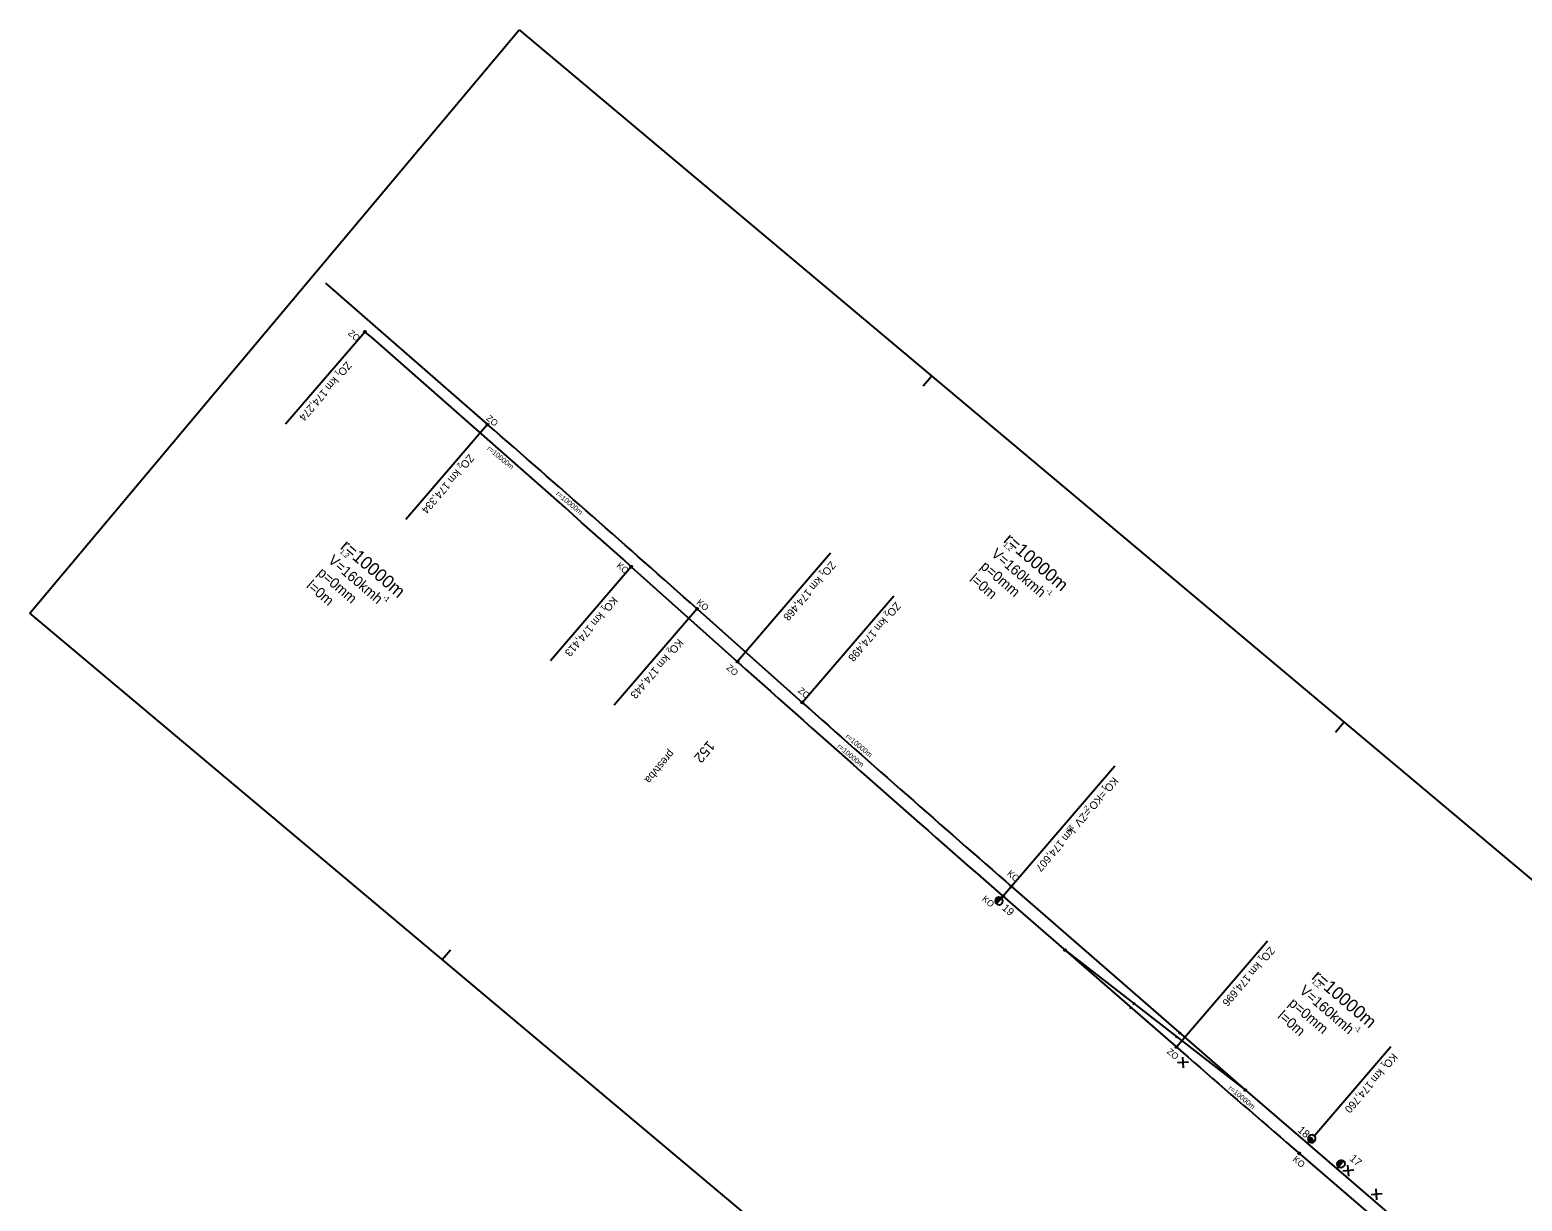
# Model space of a CAD drawing. Extents: x -473608 to -471381, y -1324122 to -1322275.
# Drawn here: x -473608 to -473026, y -1322732 to -1322275 of the extents above; entities that cross this region are included whole.
import ezdxf

# ---------------------------------------------------------------- set-up
doc = ezdxf.new("R2010")
doc.units = 0
for name, color, linetype in [('Level 1', 7, 'Continuous'), ('Level 11', 7, 'Continuous'), ('Level 6', 7, 'Continuous'), ('Level 61', 7, 'Continuous')]:
    doc.layers.add(name, color=color, linetype=linetype)

msp = doc.modelspace()

# ---------------------------------------------------------------- linework, layer by layer
at = {"layer": 'Level 1'}
for p, q in [((-473492.7, -1322373.74), (-473429.48, -1322428.74)), ((-473477.28, -1322392.6), (-473477.28, -1322392.6)), ((-473429.48, -1322428.74), (-473429.48, -1322428.74)), ((-473373.38, -1322484.25), (-473331.98, -1322521.28)), ((-473373.38, -1322484.25), (-473373.38, -1322484.25)), ((-473347.72, -1322500.65), (-473306.68, -1322537.14)), ((-473347.72, -1322500.65), (-473347.72, -1322500.65)), ((-473331.98, -1322521.28), (-473331.98, -1322521.28)), ((-473306.68, -1322537.14), (-473306.68, -1322537.14)), ((-473228.51, -1322612.55), (-473156.12, -1322675.52)), ((-473228.25, -1322612.71), (-473228.25, -1322612.71)), ((-473225, -1322608.92), (-473225, -1322608.92)), ((-473224.87, -1322609.08), (-473133.79, -1322688.32)), ((-473204.14, -1322633.75), (-473204.14, -1322633.75)), ((-473204.14, -1322633.75), (-473133.79, -1322688.32)), ((-473178.81, -1322656.46), (-473178.17, -1322655.69)), ((-473178.49, -1322656.07), (-473178.49, -1322656.07)), ((-473177.58, -1322654.95), (-473176.94, -1322654.18)), ((-473177.26, -1322654.56), (-473177.26, -1322654.56)), ((-473160.95, -1322667.88), (-473160.3, -1322667.11)), ((-473160.62, -1322667.5), (-473160.62, -1322667.5)), ((-473159.73, -1322666.4), (-473159.09, -1322665.63)), ((-473159.41, -1322666.02), (-473159.41, -1322666.02)), ((-473160.67, -1322671.54), (-473160.67, -1322671.54)), ((-473133.79, -1322688.32), (-473109.51, -1322709.21)), ((-473133.79, -1322688.32), (-473133.79, -1322688.32)), ((-473117.89, -1322708.6), (-473035.77, -1322779.3)), ((-473109.51, -1322709.21), (-473066.62, -1322746.14)), ((-473112.8, -1322713.01), (-473112.8, -1322713.01))]:
    msp.add_line(p, q, dxfattribs=at)
for points in [[(-473477.01, -1322392.29), (-473476.88, -1322392.67), (-473477.15, -1322392.97), (-473477.54, -1322392.9), (-473477.67, -1322392.52), (-473477.41, -1322392.22), (-473477.01, -1322392.29)], [(-473429.21, -1322428.44), (-473429.09, -1322428.82), (-473429.35, -1322429.12), (-473429.74, -1322429.04), (-473429.87, -1322428.66), (-473429.61, -1322428.36), (-473429.21, -1322428.44)], [(-473373.64, -1322484.55), (-473373.77, -1322484.17), (-473373.5, -1322483.87), (-473373.11, -1322483.95), (-473372.98, -1322484.33), (-473373.25, -1322484.63), (-473373.64, -1322484.55)], [(-473347.99, -1322500.94), (-473348.11, -1322500.56), (-473347.85, -1322500.27), (-473347.46, -1322500.35), (-473347.33, -1322500.73), (-473347.6, -1322501.03), (-473347.99, -1322500.94)], [(-473331.71, -1322520.98), (-473331.59, -1322521.36), (-473331.85, -1322521.66), (-473332.24, -1322521.58), (-473332.37, -1322521.2), (-473332.1, -1322520.9), (-473331.71, -1322520.98)], [(-473306.41, -1322536.84), (-473306.29, -1322537.22), (-473306.55, -1322537.52), (-473306.94, -1322537.44), (-473307.07, -1322537.06), (-473306.8, -1322536.76), (-473306.41, -1322536.84)], [(-473228.52, -1322613.02), (-473228.65, -1322612.64), (-473228.38, -1322612.34), (-473227.99, -1322612.41), (-473227.86, -1322612.79), (-473228.12, -1322613.09), (-473228.52, -1322613.02)], [(-473225.26, -1322609.23), (-473225.39, -1322608.85), (-473225.13, -1322608.55), (-473224.74, -1322608.62), (-473224.61, -1322609), (-473224.87, -1322609.3), (-473225.26, -1322609.23)], [(-473204.14, -1322634.15), (-473204.48, -1322633.95), (-473204.48, -1322633.55), (-473204.14, -1322633.35), (-473203.79, -1322633.55), (-473203.79, -1322633.95), (-473204.14, -1322634.15)], [(-473160.4, -1322671.24), (-473160.27, -1322671.61), (-473160.54, -1322671.91), (-473160.93, -1322671.84), (-473161.06, -1322671.46), (-473160.8, -1322671.16), (-473160.4, -1322671.24)], [(-473133.79, -1322688.72), (-473134.13, -1322688.52), (-473134.13, -1322688.12), (-473133.79, -1322687.92), (-473133.44, -1322688.12), (-473133.44, -1322688.52), (-473133.79, -1322688.72)], [(-473113.06, -1322713.31), (-473113.2, -1322712.93), (-473112.93, -1322712.63), (-473112.54, -1322712.7), (-473112.41, -1322713.08), (-473112.67, -1322713.38), (-473113.06, -1322713.31)]]:
    msp.add_lwpolyline(points, dxfattribs=at)
for centre, start, end in [((-480040.42, -1329937.47), 48.186756, 48.980589), ((-479992.62, -1329973.62), 48.356833, 48.98065), ((-466665.08, -1315067.93), 228.187894, 228.978408), ((-466661.92, -1315064.04), 228.357864, 228.982058), ((-466593.5, -1315130.19), 228.984525, 229.274253)]:
    msp.add_arc(centre, 10000, start, end, dxfattribs=at)
at = {"layer": 'Level 11'}
for p, q in [((-473477.24, -1322392.63), (-473508.24, -1322428.67)), ((-473429.43, -1322428.76), (-473461.35, -1322465.86)), ((-473373.39, -1322484.31), (-473404.86, -1322520.9)), ((-473295.62, -1322479), (-473331.95, -1322521.24)), ((-473270.96, -1322495.68), (-473306.62, -1322537.15)), ((-473347.8, -1322500.75), (-473380.07, -1322538.26)), ((-473184.68, -1322562.03), (-473228.3, -1322612.74)), ((-473228.3, -1322612.73), (-473230.84, -1322615.76)), ((-473228.3, -1322612.73), (-473228.3, -1322612.73)), ((-473125.19, -1322630.28), (-473160.66, -1322671.53)), ((-473157.92, -1322679.69), (-473158.24, -1322675.43)), ((-473077.05, -1322671.48), (-473106.74, -1322706)), ((-473155.95, -1322677.4), (-473160.22, -1322677.72)), ((-473108.42, -1322705.9), (-473109.02, -1322706.34)), ((-473107.66, -1322705.82), (-473108.42, -1322705.9)), ((-473106.91, -1322706.18), (-473107.66, -1322705.82)), ((-473108.86, -1322708.46), (-473109.51, -1322709.21)), ((-473109.02, -1322706.34), (-473109.37, -1322707.03)), ((-473109.37, -1322707.03), (-473109.33, -1322707.75)), ((-473109.33, -1322707.75), (-473108.86, -1322708.46)), ((-473108.86, -1322708.46), (-473109.33, -1322707.77)), ((-473108.71, -1322706.9), (-473109.15, -1322707.41)), ((-473109.15, -1322707.41), (-473109.06, -1322707.76)), ((-473109.06, -1322707.76), (-473108.37, -1322706.96)), ((-473108.08, -1322707.08), (-473108.89, -1322708.03)), ((-473108.89, -1322708.03), (-473108.86, -1322708.46)), ((-473108.86, -1322708.46), (-473107.83, -1322707.26)), ((-473108.86, -1322708.46), (-473107.83, -1322707.26)), ((-473108.44, -1322708.42), (-473108.86, -1322708.46)), ((-473108.86, -1322708.46), (-473108.11, -1322708.81)), ((-473107.62, -1322707.48), (-473108.44, -1322708.42)), ((-473108.15, -1322708.54), (-473107.46, -1322707.74)), ((-473107.79, -1322708.59), (-473108.15, -1322708.54)), ((-473108.11, -1322708.81), (-473107.4, -1322708.72)), ((-473107.34, -1322708.07), (-473107.79, -1322708.59)), ((-473107.4, -1322708.72), (-473106.75, -1322708.3)), ((-473106.45, -1322706.88), (-473106.91, -1322706.18)), ((-473106.75, -1322708.3), (-473106.44, -1322707.64)), ((-473106.44, -1322707.64), (-473106.45, -1322706.88)), ((-473098.15, -1322719), (-473095.61, -1322715.97)), ((-473093.46, -1322721.85), (-473093.78, -1322717.59)), ((-473098.15, -1322719), (-473098.15, -1322719)), ((-473091.49, -1322719.56), (-473095.75, -1322719.88)), ((-473080.49, -1322728.79), (-473084.76, -1322729.11)), ((-473082.47, -1322731.08), (-473082.79, -1322726.82))]:
    msp.add_line(p, q, dxfattribs=at)
for points in [[(-473231.15, -1322615.5), (-473230.54, -1322616.01), (-473229.78, -1322616.14), (-473229.05, -1322615.88), (-473228.54, -1322615.27), (-473228.41, -1322614.51), (-473228.67, -1322613.79), (-473229.28, -1322613.28), (-473230.04, -1322613.15), (-473230.76, -1322613.41), (-473231.28, -1322614.02), (-473231.4, -1322614.78), (-473231.15, -1322615.5), (-473231.18, -1322615.15), (-473230.79, -1322615.47), (-473230.6, -1322615.24), (-473231.25, -1322614.69), (-473231.18, -1322614.36), (-473230.41, -1322615.01), (-473230.22, -1322614.78), (-473231.1, -1322614.04), (-473230.91, -1322613.81), (-473230.02, -1322614.55), (-473229.83, -1322614.32), (-473230.71, -1322613.58), (-473230.4, -1322613.45), (-473229.64, -1322614.09), (-473229.45, -1322613.86), (-473230.1, -1322613.31), (-473229.6, -1322613.34), (-473229.25, -1322613.63)], [(-473095.91, -1322715.72), (-473095.3, -1322716.23), (-473095.04, -1322716.98), (-473095.18, -1322717.72), (-473095.68, -1322718.31), (-473096.41, -1322718.58), (-473097.17, -1322718.45), (-473097.78, -1322717.94), (-473098.03, -1322717.22), (-473097.91, -1322716.46), (-473097.39, -1322715.85), (-473096.67, -1322715.59), (-473095.91, -1322715.72), (-473096.27, -1322715.75), (-473095.88, -1322716.07), (-473096.08, -1322716.3), (-473096.73, -1322715.75), (-473097.07, -1322715.85), (-473096.27, -1322716.53), (-473096.46, -1322716.76), (-473097.34, -1322716.02), (-473097.54, -1322716.25), (-473096.65, -1322716.99), (-473096.85, -1322717.22), (-473097.73, -1322716.48), (-473097.81, -1322716.8), (-473097.04, -1322717.45), (-473097.23, -1322717.68), (-473097.88, -1322717.13), (-473097.81, -1322717.59), (-473097.42, -1322717.91)]]:
    msp.add_lwpolyline(points, dxfattribs=at)
msp.add_arc((-473108.81, -1322708.39), 1.5, 347.52757, 111.07243, dxfattribs=at)
at = {"layer": 'Level 61'}
for p, q in [((-473608.02, -1322502.42), (-473417.11, -1322274.91)), ((-473417.11, -1322274.91), (-472612.76, -1322949.83)), ((-473259.45, -1322413.72), (-473256.24, -1322409.89)), ((-472803.67, -1323177.35), (-473608.02, -1322502.42)), ((-473098.59, -1322548.71), (-473095.37, -1322544.88)), ((-473447.15, -1322637.41), (-473443.93, -1322633.58))]:
    msp.add_line(p, q, dxfattribs=at)

# ---------------------------------------------------------------- texts
at = {"layer": 'Level 11'}
for s, height, rotation, p in [('ZO', 2.5, 320, (-473484.08, -1322393.56)), ('ZO  km 174,274', 3, 229.3, (-473484.47, -1322404)), ('1', 2, 229.3, (-473488.46, -1322407.38)), ('ZO', 2.5, 320, (-473430.2, -1322426.74)), ('r=10000m', 2, 320, (-473429.78, -1322438.41)), ('ZO  km 174,334', 3, 229.3, (-473436.66, -1322440.13)), ('2', 2, 229.3, (-473440.66, -1322443.51)), ('r=10000m', 2, 320, (-473402.94, -1322456.08)), ('r=10000m', 5, 319.3, (-473228.53, -1322474.42)), ('1,2', 2, 319.3, (-473487.31, -1322478.65)), ('r=10000m', 5, 319.3, (-473487.24, -1322476.97)), ('V=160kmh', 4, 319.3, (-473233.24, -1322479.69)), ('1,2', 2, 319.3, (-473228.5, -1322475.89)), ('V=160kmh', 4, 319.3, (-473491.95, -1322482.24)), ('KO', 2.5, 320, (-473379.35, -1322484.17)), ('ZO  km 174,468', 3, 229.3, (-473295.55, -1322481.9)), ('p=0mm', 4, 319.3, (-473237.48, -1322484.61)), ('l=0m', 4, 319.3, (-473500.43, -1322492.09)), ('p=0mm', 4, 319.3, (-473496.19, -1322487.16)), ('1', 2, 229.3, (-473299.55, -1322485.28)), ('l=0m', 4, 319.3, (-473241.72, -1322489.54)), ('-1', 2, 319.3, (-473470.47, -1322496.58)), ('KO  km 174,413', 3, 229.3, (-473380.62, -1322495.68)), ('-1', 2, 319.3, (-473211.76, -1322494.03)), ('1', 2, 229.3, (-473384.61, -1322499.06)), ('KO', 2.5, 320, (-473348.17, -1322498.58)), ('ZO  km 174,498', 3, 229.3, (-473270.23, -1322497.8)), ('2', 2, 229.3, (-473274.22, -1322501.18)), ('KO  km 174,443', 3, 229.3, (-473355.03, -1322512.12)), ('2', 2, 229.3, (-473359.03, -1322515.5)), ('ZO', 2.5, 320, (-473336.51, -1322524.01)), ('ZO', 2.5, 320, (-473308.58, -1322532.93)), ('r=10000m', 2, 320, (-473293.21, -1322554.58)), ('r=10000m', 2, 320, (-473289.94, -1322550.72)), ('KO =KO =ZV  km 174,607', 3, 229.3, (-473185.3, -1322566.03)), ('1', 2, 229.3, (-473189.3, -1322569.22)), ('2', 2, 229.3, (-473195.9, -1322577.16)), ('19', 2, 229.3, (-473201.93, -1322584.53)), ('KO', 2.5, 320, (-473226.96, -1322604.24)), ('KO', 2.5, 320, (-473236.78, -1322614.17)), ('19', 3, 319.3, (-473228.99, -1322617.72)), ('ZO  km 174,696', 3, 229.3, (-473124.27, -1322632.19)), ('1', 2, 229.3, (-473128.26, -1322635.56)), ('V=160kmh', 4, 319.3, (-473113.01, -1322650.04)), ('r=10000m', 5, 319.3, (-473108.3, -1322644.77)), ('1,2', 2, 319.3, (-473108.11, -1322646.29)), ('p=0mm', 4, 319.3, (-473117.25, -1322654.97)), ('l=0m', 4, 319.3, (-473121.49, -1322659.89)), ('-1', 2, 319.3, (-473091.54, -1322664.39)), ('ZO', 2.5, 320, (-473164.65, -1322673.68)), ('KO  km 174,760', 3, 229.3, (-473076.37, -1322673.67)), ('1', 2, 229.3, (-473080.36, -1322677.04)), ('r=10000m', 2, 320, (-473140.58, -1322687.87)), ('18', 3, 319.3, (-473113.65, -1322704.32)), ('KO', 2.5, 320, (-473115.57, -1322715.69)), ('17', 3, 319.3, (-473093.36, -1322715.39))]:
    msp.add_text(s, height=height, rotation=rotation, dxfattribs=at).set_placement(p)
at = {"layer": 'Level 6'}
for s, height, p in [('152', 4, (-473343.42, -1322551.75)), ('prestvba', 3, (-473358.44, -1322555.45))]:
    msp.add_text(s, height=height, rotation=230, dxfattribs=at).set_placement(p)

doc.saveas('drawing.dxf')
